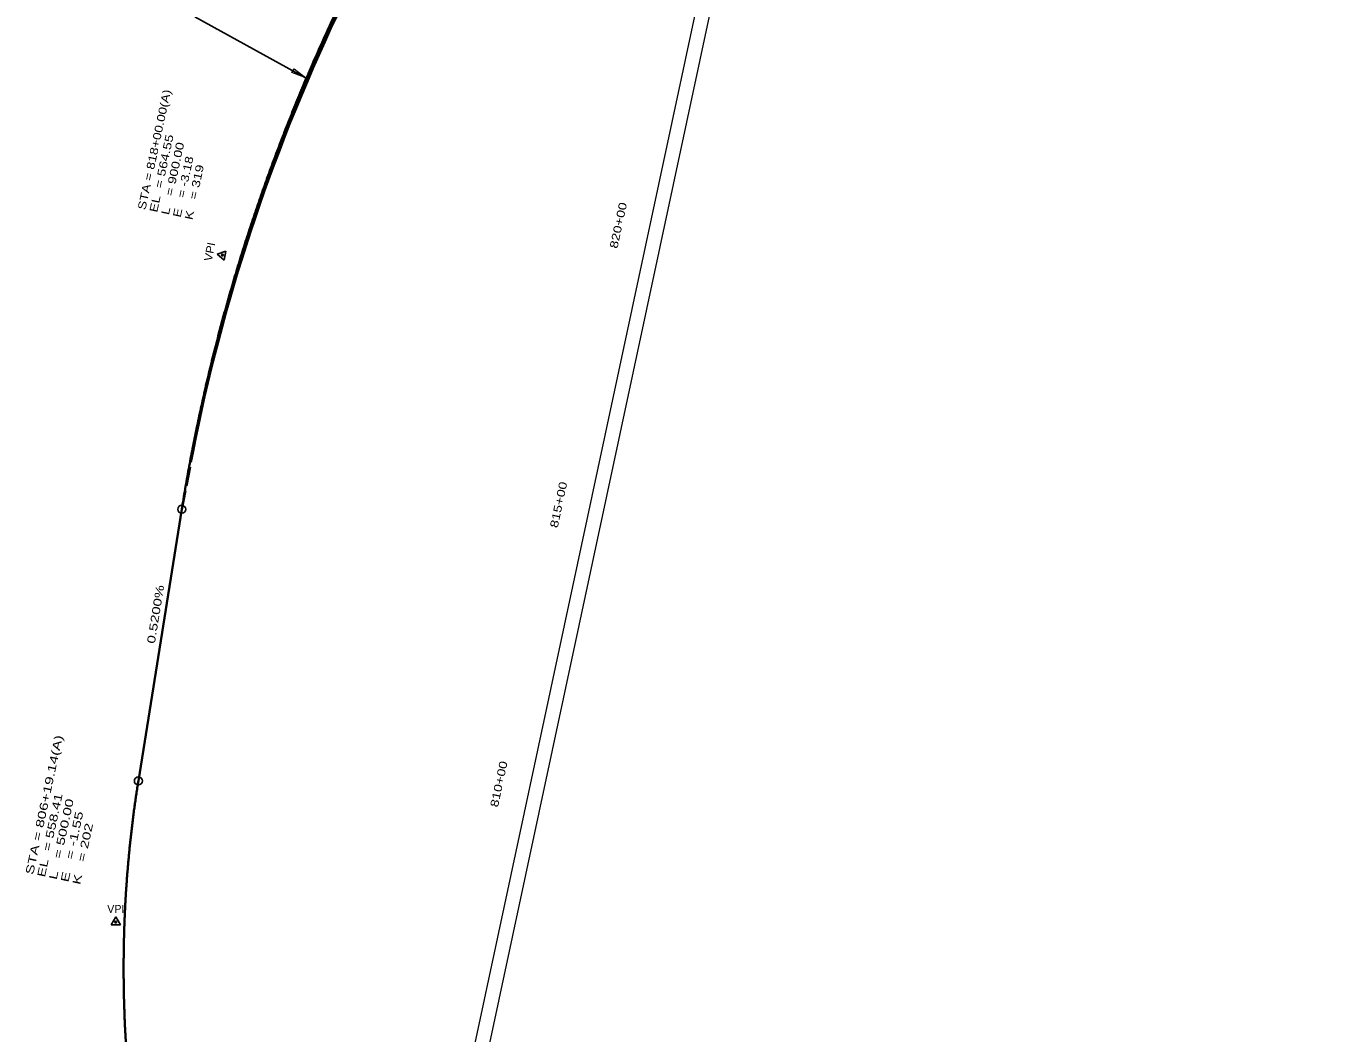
# Model space of a CAD drawing. Extents: x 2363411 to 2369702, y 6977197 to 6988655.
# Drawn here: x 2366862 to 2369126, y 6980686 to 6982449 of the extents above; entities that cross this region are included whole.
import ezdxf
from ezdxf.enums import TextEntityAlignment as Align

# ---------------------------------------------------------------- set-up
doc = ezdxf.new("R2010")
doc.units = 0
doc.header["$LTSCALE"] = 5.6
doc.linetypes.add('LONG_DASHED', pattern=[7.5, 6, -1.5])
for name, color, linetype, lineweight in [('10', 7, 'Continuous', 13), ('44', 7, 'Continuous', 25), ('61', 7, 'Continuous', 25)]:
    doc.layers.add(name, color=color, linetype=linetype, lineweight=lineweight)

msp = doc.modelspace()

# ---------------------------------------------------------------- linework, layer by layer
at = {"layer": '10'}
for p, q in [((2366907.66, 6977202.711), (2369101.754, 6987471.397)), ((2366932.108, 6977197.487), (2369126.202, 6987466.173))]:
    msp.add_line(p, q, dxfattribs=at)
at = {"layer": '44'}
for p, q in [((2367196.88, 6982049.484), (2367212.174, 6982054.693)), ((2367196.88, 6982049.484), (2367209.037, 6982038.839)), ((2367209.037, 6982038.839), (2367212.174, 6982054.693)), ((2367019.382, 6980889.37), (2367011.242, 6980875.414)), ((2367019.382, 6980889.37), (2367027.402, 6980875.344)), ((2367011.242, 6980875.414), (2367027.402, 6980875.344))]:
    msp.add_line(p, q, dxfattribs=at)
at = {"layer": '44', "lineweight": 35}
msp.add_line((2367058.858, 6981127.236), (2367134.884, 6981602.705), dxfattribs=at)
at = {"layer": '44', "linetype": 'LONG_DASHED', "lineweight": 35}
msp.add_lwpolyline([(2367135.2, 6981602.638), (2367154.036, 6981701.446), (2367158.947, 6981726.143), (2367164.054, 6981750.798), (2367169.356, 6981775.411), (2367174.853, 6981799.983), (2367180.547, 6981824.514), (2367186.436, 6981849.002), (2367192.52, 6981873.448), (2367198.8, 6981897.853), (2367205.276, 6981922.215), (2367211.947, 6981946.536), (2367218.815, 6981970.815), (2367225.877, 6981995.053), (2367233.134, 6982019.249), (2367239.634, 6982040.349), (2367247.259, 6982064.466), (2367255.078, 6982088.541), (2367263.095, 6982112.576), (2367271.307, 6982136.568), (2367279.714, 6982160.518), (2367288.315, 6982184.426), (2367297.114, 6982208.295), (2367306.107, 6982232.119), (2367315.298, 6982255.902), (2367324.683, 6982279.643), (2367334.263, 6982303.343), (2367344.038, 6982327.001), (2367354.01, 6982350.617), (2367364.179, 6982374.191), (2367374.541, 6982397.725), (2367385.099, 6982421.215), (2367395.853, 6982444.663), (2367405.406, 6982465.107)], dxfattribs=at)
at = {"layer": '44'}
for centre, radius in [((2367206.031, 6982047.662), 1.5), ((2367134.884, 6981602.706), 7), ((2367058.857, 6981127.236), 7), ((2367019.332, 6980880.039), 1.5)]:
    msp.add_circle(centre, radius, dxfattribs=at)
at = {"layer": '44', "lineweight": 35}
for points in [[(2367134.884, 6981602.705), (2367137.779, 6981620.493), (2367140.773, 6981638.26), (2367143.868, 6981656.005), (2367147.062, 6981673.729), (2367150.355, 6981691.431), (2367153.747, 6981709.113), (2367157.24, 6981726.773), (2367160.831, 6981744.412), (2367164.522, 6981762.029), (2367168.312, 6981779.626), (2367172.2, 6981797.201), (2367176.19, 6981814.755), (2367180.278, 6981832.288), (2367184.466, 6981849.8), (2367188.753, 6981867.29), (2367193.138, 6981884.759), (2367197.625, 6981902.207), (2367202.209, 6981919.634), (2367206.893, 6981937.039), (2367211.678, 6981954.423), (2367216.561, 6981971.786), (2367221.545, 6981989.127), (2367226.626, 6982006.448), (2367231.807, 6982023.747), (2367237.088, 6982041.025), (2367242.469, 6982058.282), (2367247.949, 6982075.517), (2367253.527, 6982092.732), (2367259.205, 6982109.925), (2367264.983, 6982127.096), (2367270.86, 6982144.247), (2367276.837, 6982161.376), (2367282.912, 6982178.484), (2367289.089, 6982195.571), (2367295.363, 6982212.637), (2367301.737, 6982229.681), (2367308.211, 6982246.704), (2367314.783, 6982263.706), (2367321.456, 6982280.687), (2367328.227, 6982297.646), (2367335.098, 6982314.584), (2367342.069, 6982331.501), (2367349.137, 6982348.397), (2367356.308, 6982365.271), (2367363.576, 6982382.125), (2367370.943, 6982398.957), (2367378.411, 6982415.768), (2367385.978, 6982432.557), (2367393.643, 6982449.326), (2367401.41, 6982466.072)], [(2367040.455, 6980619.882), (2367039.634, 6980630.283), (2367038.862, 6980640.673), (2367038.139, 6980651.054), (2367037.463, 6980661.424), (2367036.838, 6980671.783), (2367036.26, 6980682.132), (2367035.73, 6980692.471), (2367035.248, 6980702.8), (2367034.816, 6980713.118), (2367034.432, 6980723.426), (2367034.096, 6980733.723), (2367033.809, 6980744.01), (2367033.571, 6980754.287), (2367033.382, 6980764.553), (2367033.24, 6980774.809), (2367033.147, 6980785.055), (2367033.103, 6980795.29), (2367033.107, 6980805.515), (2367033.159, 6980815.729), (2367033.261, 6980825.933), (2367033.41, 6980836.127), (2367033.609, 6980846.31), (2367033.856, 6980856.483), (2367034.15, 6980866.646), (2367034.495, 6980876.798), (2367034.886, 6980886.94), (2367035.327, 6980897.072), (2367035.817, 6980907.193), (2367036.355, 6980917.303), (2367036.941, 6980927.404), (2367037.575, 6980937.494), (2367038.258, 6980947.574), (2367038.991, 6980957.643), (2367039.772, 6980967.702), (2367040.602, 6980977.751), (2367041.479, 6980987.789), (2367042.404, 6980997.817), (2367043.379, 6981007.834), (2367044.403, 6981017.841), (2367045.473, 6981027.838), (2367046.594, 6981037.824), (2367047.763, 6981047.8), (2367048.98, 6981057.766), (2367050.244, 6981067.722), (2367051.559, 6981077.667), (2367052.921, 6981087.601), (2367054.334, 6981097.525), (2367055.794, 6981107.439), (2367057.3, 6981117.343), (2367058.858, 6981127.236)]]:
    msp.add_spline(points, degree=3, dxfattribs=at)
at = {"layer": '61'}
msp.add_line((2367351.13, 6982358.149), (2367157.409, 6982464.85), dxfattribs=at)
at = {"layer": '61', "lineweight": 13}
msp.add_lwpolyline([(2367331.323, 6982373.502), (2367351.58, 6982357.869), (2367327.477, 6982367.088)], close=True, dxfattribs=at)

# ---------------------------------------------------------------- texts
at = {"layer": '44'}
for s, rotation, width, p in [('STA = 818+00.00(A)', 77.939, 1.25, (2367071.185, 6982125.915)), ('EL  = 564.55', 77.939, 1.3, (2367091.722, 6982121.527)), ('L   = 900.00', 77.939, 1.3, (2367112.259, 6982117.139)), ('E   = -3.18', 77.939, 1.25, (2367132.797, 6982112.751)), ('K   = 319', 77.939, 1.3, (2367153.334, 6982108.363)), ('0.5200% ', 80.799, 1.4, (2367087.586, 6981366.789)), ('STA = 806+19.14(A)', 77.939, 1.45, (2366874.808, 6980962.232)), ('EL  = 558.41', 77.939, 1.4, (2366895.345, 6980957.844)), ('L   = 500.00', 77.939, 1.45, (2366915.882, 6980953.456)), ('E   = -1.55', 77.939, 1.45, (2366936.42, 6980949.068)), ('K   = 202', 77.939, 1.45, (2366956.957, 6980944.68))]:
    msp.add_text(s, height=14, rotation=rotation, dxfattribs=dict(at, width=width)).set_placement(p)
for s, rotation, width, p in [('820+00', 77.939, 1.3, (2367905.335, 6982098.237)), ('VPI', 78.803, 1.1, (2367190.409, 6982052.169)), ('815+00', 77.939, 1.3, (2367800.854, 6981609.252)), ('810+00', 77.939, 1.3, (2367696.373, 6981120.267))]:
    msp.add_text(s, height=14, rotation=rotation, dxfattribs=dict(at, width=width)).set_placement(p, align=Align.CENTER)
msp.add_text('VPI', height=14, rotation=359.753, dxfattribs=at).set_placement((2367019.435, 6980896.239), align=Align.CENTER)

doc.saveas('drawing.dxf')
